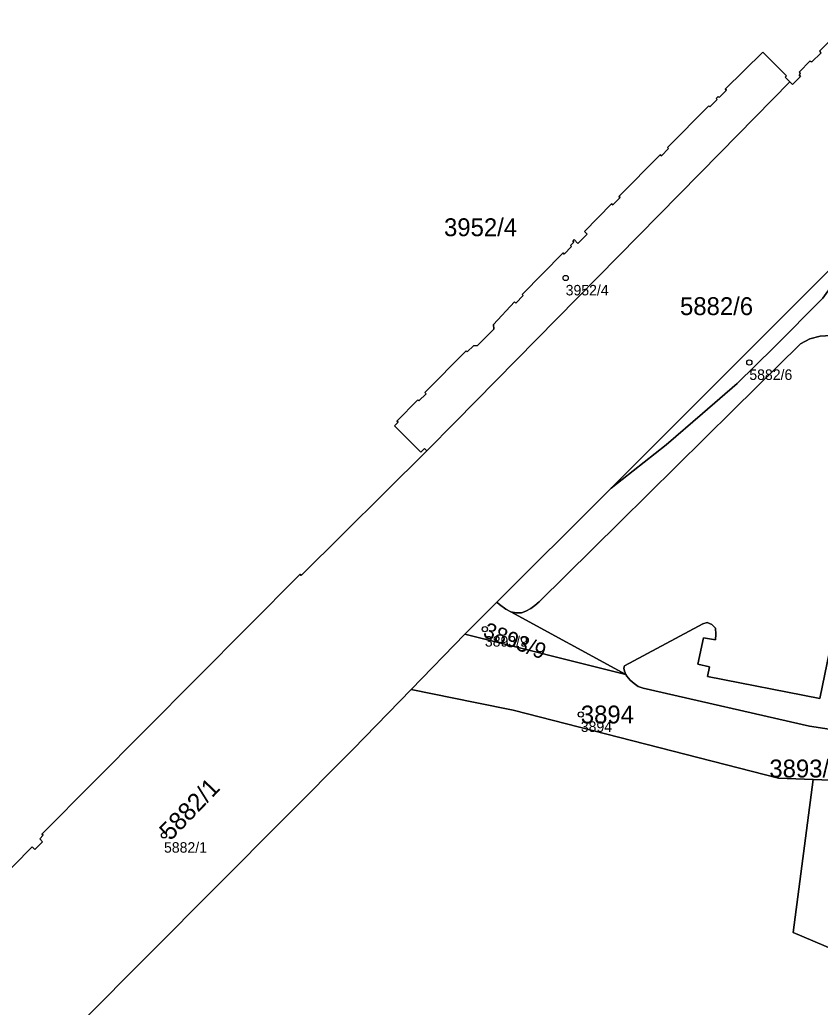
# Model space of a CAD drawing. Extents: x -690132 to -685994, y -975441 to -972444.
# Drawn here: x -688503 to -688426.8, y -974917.9 to -974823.9 of the extents above; entities that cross this region are included whole.
import ezdxf

# ---------------------------------------------------------------- set-up
doc = ezdxf.new("R2010")
doc.units = 0
for name, color, linetype in [('Definiční body', 7, 'Continuous'), ('Hranice parcel', 7, 'Continuous'), ('Parcelní čísla', 7, 'Continuous'), ('Polygon budovy', 7, 'Continuous'), ('Polygon parcely', 7, 'Continuous')]:
    doc.layers.add(name, color=color, linetype=linetype)

msp = doc.modelspace()

# ---------------------------------------------------------------- linework, layer by layer
at = {"layer": 'Definiční body'}
for centre in [(-688451.02, -974848.51), (-688433.54, -974856.55), (-688458.71, -974881.92), (-688449.58, -974890.04), (-688489.25, -974901.53)]:
    msp.add_circle(centre, 0.25, dxfattribs=at)
at = {"layer": 'Hranice parcel'}
for p, q in [((-688457.56, -974879.34), (-688460.62, -974882.4)), ((-688456.24, -974880.27), (-688445.28, -974886.22)), ((-688460.62, -974882.4), (-688465.73, -974887.65)), ((-688460.62, -974882.4), (-688445.28, -974886.22)), ((-688427.47, -974896.22), (-688401.52, -974897.21))]:
    msp.add_line(p, q, dxfattribs=at)
for points in [[(-688423.86, -974823.94), (-688426.82, -974826.91), (-688426.75, -974827.12), (-688427.58, -974827.95), (-688427.79, -974827.88), (-688428.78, -974828.88), (-688428.71, -974829.09), (-688428.81, -974829.19), (-688428.67, -974829.33), (-688429.44, -974830.1), (-688429.69, -974829.85)], [(-688429.69, -974829.85), (-688430.13, -974829.41), (-688429.99, -974829.27), (-688432.26, -974827.01), (-688435.83, -974830.53), (-688435.72, -974830.64), (-688436.41, -974831.33), (-688436.52, -974831.23), (-688436.71, -974831.42), (-688436.6, -974831.53), (-688437.29, -974832.22), (-688437.4, -974832.12), (-688441.32, -974836.08), (-688441.22, -974836.19), (-688441.91, -974836.89), (-688442.02, -974836.78), (-688445.95, -974840.75), (-688445.84, -974840.86), (-688446.54, -974841.56), (-688446.65, -974841.46), (-688449.23, -974844.07), (-688448.98, -974844.33), (-688449.86, -974845.22), (-688450.22, -974844.86), (-688450.34, -974844.98), (-688450.24, -974845.09), (-688450.56, -974845.42), (-688450.45, -974845.52), (-688451.15, -974846.23), (-688451.26, -974846.12), (-688455.17, -974850.07), (-688455.06, -974850.17), (-688455.77, -974850.89), (-688455.88, -974850.79), (-688457.9, -974852.93), (-688457.87, -974853.37), (-688459.42, -974854.94), (-688459.8, -974854.95), (-688460.39, -974855.55), (-688460.49, -974855.45), (-688464.41, -974859.41), (-688464.3, -974859.52), (-688464.99, -974860.21), (-688465.1, -974860.11), (-688467.09, -974862.12), (-688466.97, -974862.24), (-688467.31, -974862.58), (-688464.79, -974865.07), (-688464.45, -974864.73), (-688464.24, -974864.94)], [(-688429.69, -974829.85), (-688436.32, -974836.59), (-688461.55, -974862.21), (-688464.24, -974864.94)], [(-688446.69, -974868.49), (-688441.14, -974862.95), (-688433.15, -974854.96), (-688427.88, -974849.7), (-688422.52, -974844.35)], [(-688422.52, -974844.35), (-688422.82, -974844.83), (-688424.94, -974848.19), (-688426.55, -974850.42), (-688431.19, -974855.08), (-688434.71, -974858.56), (-688437.99, -974861.4), (-688441.47, -974864.38), (-688446.69, -974868.49)], [(-688456.24, -974880.27), (-688455.74, -974880.38), (-688455.24, -974880.35), (-688454.82, -974880.2), (-688454.35, -974879.94), (-688453.94, -974879.66), (-688453.55, -974879.32), (-688445.88, -974871.74), (-688435.09, -974861.07), (-688428.66, -974854.77), (-688427.77, -974854.31), (-688426.79, -974854.03), (-688425.77, -974853.98)], [(-688464.24, -974864.94), (-688476.18, -974876.81), (-688476.28, -974876.7), (-688500.87, -974901.43), (-688500.76, -974901.53), (-688501.08, -974901.87), (-688500.82, -974902.16), (-688501.55, -974902.89), (-688501.81, -974902.63), (-688507.13, -974908.03), (-688506.89, -974908.27), (-688507.62, -974909.01), (-688507.86, -974908.77), (-688513.18, -974914.13), (-688512.94, -974914.37), (-688513.66, -974915.09), (-688513.9, -974914.85), (-688514.29, -974915.23)], [(-688446.69, -974868.49), (-688447.3, -974869.1), (-688457.56, -974879.34)], [(-688457.56, -974879.34), (-688457.32, -974879.56), (-688456.71, -974880.01), (-688456.24, -974880.27)], [(-688445.28, -974886.22), (-688445.41, -974885.93), (-688445.49, -974885.63), (-688445.41, -974885.4), (-688438.39, -974881.62), (-688437.98, -974881.4), (-688437.55, -974881.3), (-688437.12, -974881.46), (-688436.77, -974881.82), (-688436.72, -974882.4), (-688436.77, -974882.94), (-688437.91, -974882.73), (-688438.45, -974885.26), (-688437.33, -974885.5), (-688437.51, -974886.41), (-688426.84, -974888.51), (-688425.91, -974884.05)], [(-688445.28, -974886.22), (-688445.21, -974886.38), (-688444.89, -974886.76), (-688444.5, -974887.08), (-688444.11, -974887.36), (-688443.63, -974887.54), (-688427.8, -974891.15), (-688424.69, -974891.63)], [(-688465.73, -974887.65), (-688471.23, -974893.35), (-688497.21, -974919.41)], [(-688465.73, -974887.65), (-688459.63, -974888.89), (-688456.01, -974889.62), (-688430.75, -974896.09), (-688427.47, -974896.22)], [(-688412.69, -974917.84), (-688429.38, -974910.79), (-688427.47, -974896.22)]]:
    msp.add_lwpolyline(points, dxfattribs=at)
at = {"layer": 'Polygon budovy'}
for points in [[(-688450.45, -974845.52), (-688450.56, -974845.42), (-688450.24, -974845.09), (-688450.34, -974844.98), (-688450.22, -974844.86), (-688449.86, -974845.22), (-688448.98, -974844.33), (-688449.23, -974844.07), (-688446.65, -974841.46), (-688446.54, -974841.56), (-688445.84, -974840.86), (-688445.95, -974840.75), (-688442.02, -974836.78), (-688441.91, -974836.89), (-688441.22, -974836.19), (-688441.32, -974836.08), (-688437.4, -974832.12), (-688437.29, -974832.22), (-688436.6, -974831.53), (-688436.71, -974831.42), (-688436.52, -974831.23), (-688436.41, -974831.33), (-688435.72, -974830.64), (-688435.83, -974830.53), (-688432.26, -974827.01), (-688429.99, -974829.27), (-688430.13, -974829.41), (-688429.69, -974829.85), (-688429.44, -974830.1), (-688428.67, -974829.33), (-688428.81, -974829.19), (-688428.71, -974829.09), (-688428.78, -974828.88), (-688427.79, -974827.88), (-688427.58, -974827.95), (-688426.75, -974827.12), (-688426.82, -974826.91), (-688423.86, -974823.94)], [(-688507.13, -974908.03), (-688501.81, -974902.63), (-688501.55, -974902.89), (-688500.82, -974902.16), (-688501.08, -974901.87), (-688500.76, -974901.53), (-688500.87, -974901.43), (-688476.28, -974876.7), (-688476.18, -974876.81), (-688464.24, -974864.94), (-688464.45, -974864.73), (-688464.79, -974865.07), (-688467.31, -974862.58), (-688466.97, -974862.24), (-688467.09, -974862.12), (-688465.1, -974860.11), (-688464.99, -974860.21), (-688464.3, -974859.52), (-688464.41, -974859.41), (-688460.49, -974855.45), (-688460.39, -974855.55), (-688459.8, -974854.95), (-688459.42, -974854.94), (-688457.87, -974853.37), (-688457.9, -974852.93), (-688455.88, -974850.79), (-688455.77, -974850.89), (-688455.06, -974850.17), (-688455.17, -974850.07), (-688451.26, -974846.12), (-688451.15, -974846.23), (-688450.45, -974845.52)]]:
    msp.add_lwpolyline(points, dxfattribs=at)
at = {"layer": 'Polygon parcely'}
for points in [[(-688423.86, -974823.94), (-688426.82, -974826.91), (-688426.75, -974827.12), (-688427.58, -974827.95), (-688427.79, -974827.88), (-688428.78, -974828.88), (-688428.71, -974829.09), (-688428.81, -974829.19), (-688428.67, -974829.33), (-688429.44, -974830.1), (-688429.69, -974829.85), (-688436.32, -974836.59), (-688461.55, -974862.21), (-688464.24, -974864.94), (-688476.18, -974876.81), (-688476.28, -974876.7), (-688500.87, -974901.43), (-688500.76, -974901.53), (-688501.08, -974901.87), (-688500.82, -974902.16), (-688501.55, -974902.89), (-688501.81, -974902.63), (-688507.13, -974908.03)], [(-688507.13, -974908.03), (-688501.81, -974902.63), (-688501.55, -974902.89), (-688500.82, -974902.16), (-688501.08, -974901.87), (-688500.76, -974901.53), (-688500.87, -974901.43), (-688476.28, -974876.7), (-688476.18, -974876.81), (-688464.24, -974864.94), (-688464.45, -974864.73), (-688464.79, -974865.07), (-688467.31, -974862.58), (-688466.97, -974862.24), (-688467.09, -974862.12), (-688465.1, -974860.11), (-688464.99, -974860.21), (-688464.3, -974859.52), (-688464.41, -974859.41), (-688460.49, -974855.45), (-688460.39, -974855.55), (-688459.8, -974854.95), (-688459.42, -974854.94), (-688457.87, -974853.37), (-688457.9, -974852.93), (-688455.88, -974850.79), (-688455.77, -974850.89), (-688455.06, -974850.17), (-688455.17, -974850.07), (-688451.26, -974846.12), (-688451.15, -974846.23), (-688450.45, -974845.52), (-688450.56, -974845.42), (-688450.24, -974845.09), (-688450.34, -974844.98), (-688450.22, -974844.86), (-688449.86, -974845.22), (-688448.98, -974844.33), (-688449.23, -974844.07), (-688446.65, -974841.46), (-688446.54, -974841.56), (-688445.84, -974840.86), (-688445.95, -974840.75), (-688442.02, -974836.78), (-688441.91, -974836.89), (-688441.22, -974836.19), (-688441.32, -974836.08), (-688437.4, -974832.12), (-688437.29, -974832.22), (-688436.6, -974831.53), (-688436.71, -974831.42), (-688436.52, -974831.23), (-688436.41, -974831.33), (-688435.72, -974830.64), (-688435.83, -974830.53), (-688432.26, -974827.01), (-688429.99, -974829.27), (-688430.13, -974829.41), (-688429.69, -974829.85), (-688429.44, -974830.1), (-688428.67, -974829.33), (-688428.81, -974829.19), (-688428.71, -974829.09), (-688428.78, -974828.88), (-688427.79, -974827.88), (-688427.58, -974827.95), (-688426.75, -974827.12), (-688426.82, -974826.91), (-688423.86, -974823.94)], [(-688497.21, -974919.41), (-688471.23, -974893.35), (-688465.73, -974887.65), (-688460.62, -974882.4), (-688457.56, -974879.34), (-688447.3, -974869.1), (-688446.69, -974868.49), (-688441.14, -974862.95), (-688433.15, -974854.96), (-688427.88, -974849.7), (-688422.52, -974844.35)], [(-688426.55, -974850.42), (-688431.19, -974855.08), (-688434.71, -974858.56), (-688437.99, -974861.4), (-688441.47, -974864.38), (-688446.69, -974868.49), (-688447.3, -974869.1), (-688457.56, -974879.34), (-688457.32, -974879.56), (-688456.71, -974880.01), (-688456.24, -974880.27), (-688455.74, -974880.38), (-688455.24, -974880.35), (-688454.82, -974880.2), (-688454.35, -974879.94), (-688453.94, -974879.66), (-688453.55, -974879.32), (-688445.88, -974871.74), (-688435.09, -974861.07), (-688428.66, -974854.77), (-688427.77, -974854.31), (-688426.79, -974854.03), (-688425.77, -974853.98)], [(-688425.77, -974853.98), (-688426.79, -974854.03), (-688427.77, -974854.31), (-688428.66, -974854.77), (-688435.09, -974861.07), (-688445.88, -974871.74), (-688453.55, -974879.32), (-688453.94, -974879.66), (-688454.35, -974879.94), (-688454.82, -974880.2), (-688455.24, -974880.35), (-688455.74, -974880.38), (-688456.24, -974880.27), (-688445.28, -974886.22), (-688445.41, -974885.93), (-688445.49, -974885.63), (-688445.41, -974885.4), (-688438.39, -974881.62), (-688437.98, -974881.4), (-688437.55, -974881.3), (-688437.12, -974881.46), (-688436.77, -974881.82), (-688436.72, -974882.4), (-688436.77, -974882.94), (-688437.91, -974882.73), (-688438.45, -974885.26), (-688437.33, -974885.5), (-688437.51, -974886.41), (-688426.84, -974888.51), (-688425.91, -974884.05)], [(-688425.91, -974884.05), (-688426.84, -974888.51), (-688437.51, -974886.41), (-688437.33, -974885.5), (-688438.45, -974885.26), (-688437.91, -974882.73), (-688436.77, -974882.94), (-688436.72, -974882.4), (-688436.77, -974881.82), (-688437.12, -974881.46), (-688437.55, -974881.3), (-688437.98, -974881.4), (-688438.39, -974881.62), (-688445.41, -974885.4), (-688445.49, -974885.63), (-688445.41, -974885.93), (-688445.28, -974886.22), (-688445.21, -974886.38), (-688444.89, -974886.76), (-688444.5, -974887.08), (-688444.11, -974887.36), (-688443.63, -974887.54), (-688427.8, -974891.15), (-688424.69, -974891.63)], [(-688424.69, -974891.63), (-688427.8, -974891.15), (-688443.63, -974887.54), (-688444.11, -974887.36), (-688444.5, -974887.08), (-688444.89, -974886.76), (-688445.21, -974886.38), (-688445.28, -974886.22), (-688460.62, -974882.4), (-688465.73, -974887.65), (-688459.63, -974888.89), (-688456.01, -974889.62), (-688430.75, -974896.09), (-688427.47, -974896.22), (-688401.52, -974897.21)]]:
    msp.add_lwpolyline(points, dxfattribs=at)
for points in [[(-688429.99, -974829.27), (-688432.26, -974827.01), (-688435.83, -974830.53), (-688435.72, -974830.64), (-688436.41, -974831.33), (-688436.52, -974831.23), (-688436.71, -974831.42), (-688436.6, -974831.53), (-688437.29, -974832.22), (-688437.4, -974832.12), (-688441.32, -974836.08), (-688441.22, -974836.19), (-688441.91, -974836.89), (-688442.02, -974836.78), (-688445.95, -974840.75), (-688445.84, -974840.86), (-688446.54, -974841.56), (-688446.65, -974841.46), (-688449.23, -974844.07), (-688448.98, -974844.33), (-688449.86, -974845.22), (-688450.22, -974844.86), (-688450.34, -974844.98), (-688450.24, -974845.09), (-688450.56, -974845.42), (-688450.45, -974845.52), (-688451.15, -974846.23), (-688451.26, -974846.12), (-688455.17, -974850.07), (-688455.06, -974850.17), (-688455.77, -974850.89), (-688455.88, -974850.79), (-688457.9, -974852.93), (-688457.87, -974853.37), (-688459.42, -974854.94), (-688459.8, -974854.95), (-688460.39, -974855.55), (-688460.49, -974855.45), (-688464.41, -974859.41), (-688464.3, -974859.52), (-688464.99, -974860.21), (-688465.1, -974860.11), (-688467.09, -974862.12), (-688466.97, -974862.24), (-688467.31, -974862.58), (-688464.79, -974865.07), (-688464.45, -974864.73), (-688464.24, -974864.94), (-688461.55, -974862.21), (-688436.32, -974836.59), (-688429.69, -974829.85), (-688430.13, -974829.41)], [(-688446.69, -974868.49), (-688441.47, -974864.38), (-688437.99, -974861.4), (-688434.71, -974858.56), (-688431.19, -974855.08), (-688426.55, -974850.42), (-688424.94, -974848.19), (-688422.82, -974844.83), (-688422.52, -974844.35), (-688427.88, -974849.7), (-688433.15, -974854.96), (-688441.14, -974862.95)], [(-688445.28, -974886.22), (-688456.24, -974880.27), (-688456.71, -974880.01), (-688457.32, -974879.56), (-688457.56, -974879.34), (-688460.62, -974882.4)], [(-688451.14, -974965.75), (-688447.62, -974969.3), (-688443.5, -974965.22), (-688409.94, -974931.98), (-688410.59, -974931.47), (-688417.41, -974926.21), (-688412.69, -974917.84), (-688429.38, -974910.79), (-688427.47, -974896.22), (-688430.75, -974896.09), (-688456.01, -974889.62), (-688459.63, -974888.89), (-688465.73, -974887.65), (-688471.23, -974893.35), (-688497.21, -974919.41), (-688493.29, -974923.25)], [(-688401.52, -974897.21), (-688427.47, -974896.22), (-688429.38, -974910.79), (-688412.69, -974917.84), (-688405.83, -974905.18)]]:
    msp.add_lwpolyline(points, close=True, dxfattribs=at)

# ---------------------------------------------------------------- texts
at = {"layer": 'Definiční body'}
for s, p in [('3952/4', (-688451.02, -974850.166)), ('5882/6', (-688433.54, -974858.206)), ('3893/9', (-688458.71, -974883.576)), ('3894', (-688449.58, -974891.696)), ('5882/1', (-688489.25, -974903.186))]:
    msp.add_text(s, height=1, dxfattribs=at).set_placement(p)
at = {"layer": 'Parcelní čísla'}
for s, p in [('3952/4', (-688462.597, -974844.53)), ('5882/6', (-688440.137, -974852.04)), ('3894', (-688449.58, -974890.89)), ('3893/8', (-688431.635, -974896.028))]:
    msp.add_text(s, height=1.7, dxfattribs=at).set_placement(p)
for s, height, rotation, p in [('3893/9', 1.5, 339, (-688458.978, -974882.62)), ('5882/1', 1.7, 46, (-688488.638, -974902.12))]:
    msp.add_text(s, height=height, rotation=rotation, dxfattribs=at).set_placement(p)

doc.saveas('drawing.dxf')
